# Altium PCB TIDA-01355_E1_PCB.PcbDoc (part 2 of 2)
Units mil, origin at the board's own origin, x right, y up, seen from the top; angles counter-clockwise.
Board outline 2150 x 1600 mil, 4 copper layers (Top Layer, GND, PWR, Bottom Layer), stack 59.906 mil thick; 85 components, 55 nets, 272 pads, 126 vias.
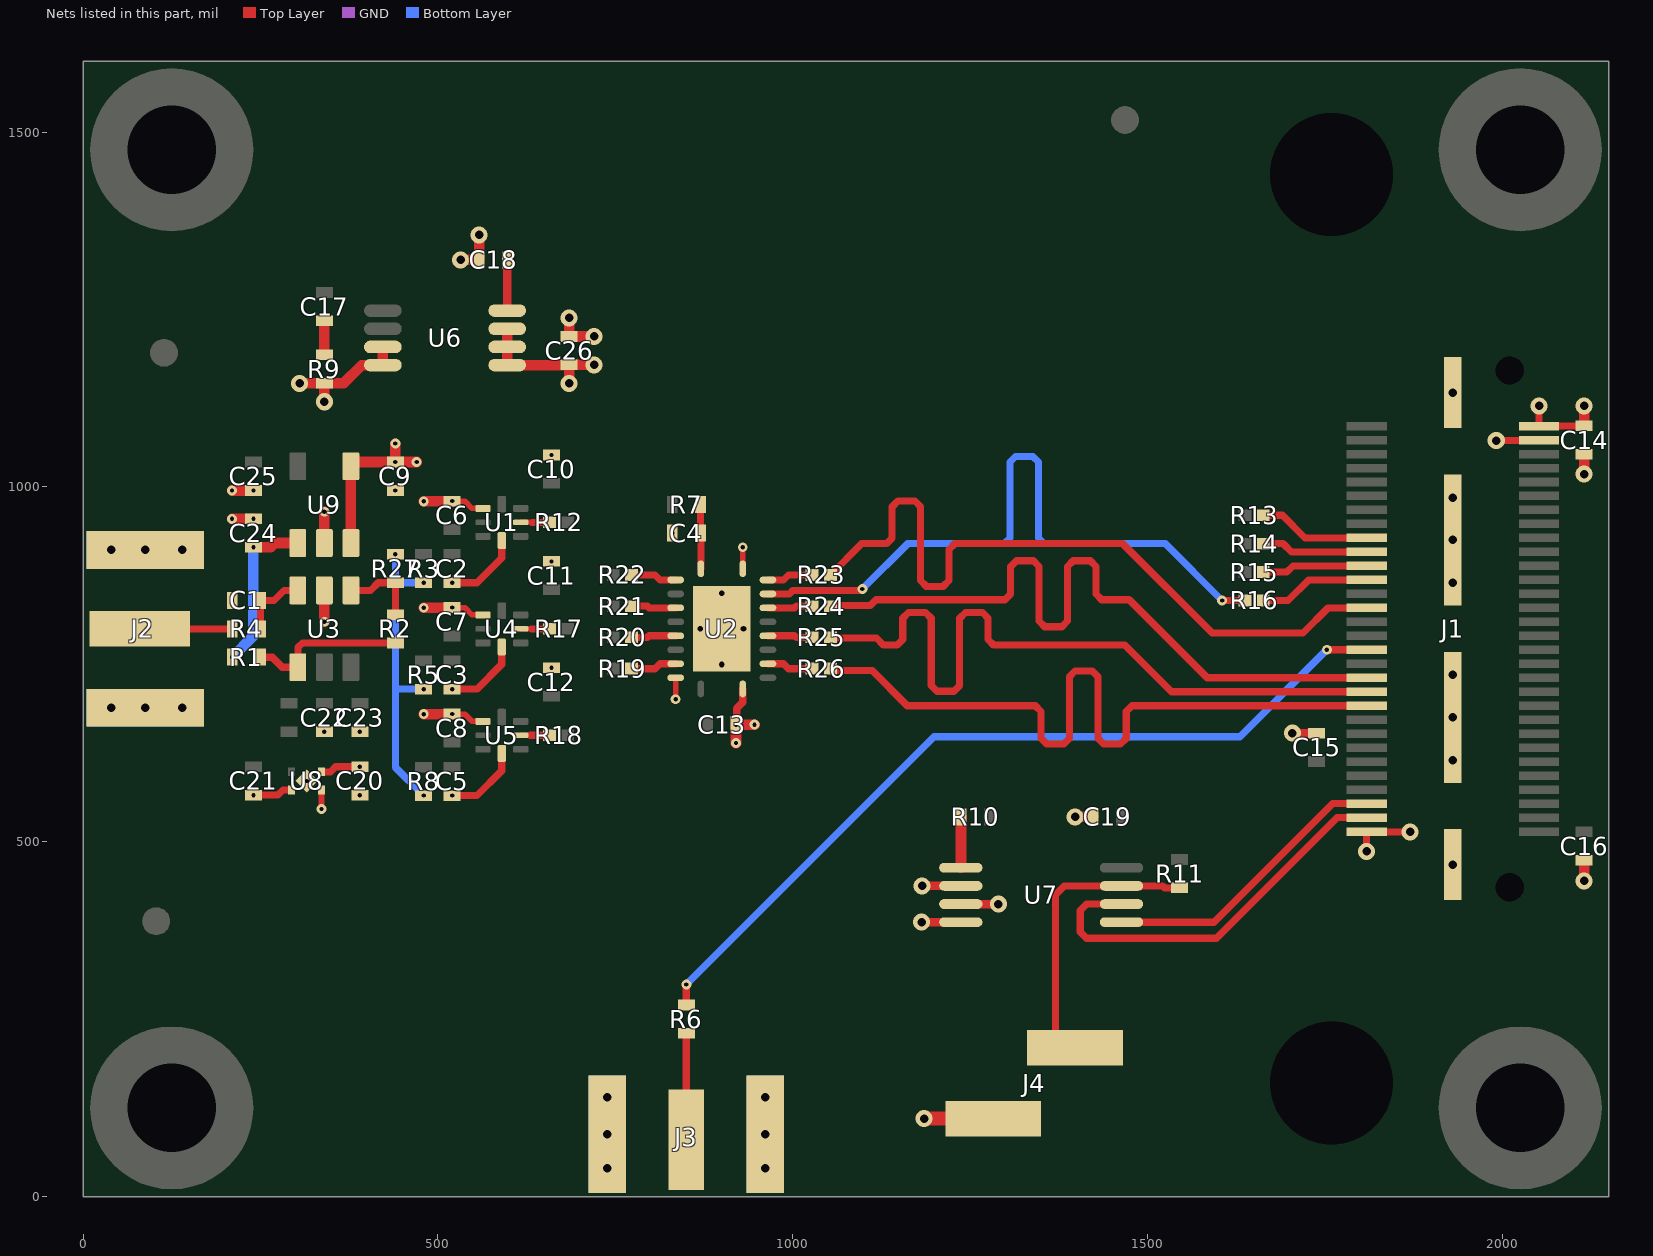
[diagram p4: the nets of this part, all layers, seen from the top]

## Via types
v1: diameter 14, hole 6, Top Layer to Bottom Layer, 70 vias
v2: diameter 24, hole 12, Top Layer to Bottom Layer, 52 vias
v3: diameter 19.68, hole 7.87, Top Layer to Bottom Layer, 4 vias

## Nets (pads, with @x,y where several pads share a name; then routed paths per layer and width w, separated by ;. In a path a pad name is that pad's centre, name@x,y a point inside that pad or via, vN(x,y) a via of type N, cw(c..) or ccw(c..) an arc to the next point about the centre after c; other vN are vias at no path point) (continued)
EVM_ID_SCL: J1.58 U7.6 | length 569.7
  Top Layer w10.06: U7.6@1463.19,412.2 1414.2,412.2 1405,403 1405,373 1414.02,363.98 1596.98,363.98 1767.1,534.1 J1.58@1808.5,534.1
EVM_ID_SDA: J1.56 U7.5 | length 414.6
  Top Layer w10.06: U7.5@1463.19,386.61 1593.61,386.61 1760.8,553.8 J1.56@1808.5,553.8
EVM_REG_5V5: C9.1 C14.1 C20.1 C26.1 J1.1 U6.1 U6.2 U6.3 U8.3 U8.4 U9.3 U9.4 | length 628.3
  Top Layer w8: v1(336.06,546) U8.3@336.06,572.87
  Top Layer w10: U8.4@336.06,598.46 348.46,598.46 355.67,605.67 v1(390,605.67) ; J1.1@2051.5,1085.7 C14.1@2115,1085.7 ; J1.1@2051.5,1086 v2(2051.5,1114)
  Top Layer w15: U9.3@377.4,920.87 U9.4@377.4,1029.13 ; U9.4@379,1035 v1(440,1035) ; v1(440,1061) v1(440,1035) ; v1(470,1035) v1(440,1035) ; U6.3@597.6,1222.8 U6.2@597.6,1197.21 U6.1@597.6,1171.62 684.62,1171.62 C26.1@685,1172 ; v2(685,1146) C26.1@685,1172 ; v2(720,1172) C26.1@685,1172 ; C14.1@2115,1086 v2(2115,1114)
FB_SCLK: C4.1 R7.2 U2.11 | length 90.5
  Top Layer w10.06: R7.2@870,975 C4.1@870,935 870.48,934.52 U2.11@870.48,884.65
GND: C1.2 C2.2 C3.2 C4.2 C5.2 C6.2 C7.2 C8.2 C9.2 C10.2 C11.2 C12.2 C13.2 C14.2 C15.2 C16.2 C18.2 C19.2 C20.2 C21.2 C22.2 C23.2 C24.2 C25.2 C26.2 J1.3 J1.60 J1.MP1 J1.MP2 J1.MP3 J1.MP4 J2.2 J2.3 J2.4 J2.5 J3.2 J3.3 J3.4 J3.5 J4.2 R9.1 U1.5 U1.8 U2.1 U2.10 U2.19 U2.21 U3.2 U4.5 U4.8 U5.5 U5.8 U6.7 U6.8 U7.2 U7.3 U7.4 U8.2 U8.5 U9.2 | length 1793.7
  Top Layer w8: C8.2@520,679.69 538,679.69 548,669.69 U5.5@563.43,669.69 ; C7.2@520,829.69 538,829.69 548,819.69 U4.5@563.43,819.69 ; C6.2@520,979.69 538,979.69 548,969.69 U1.5@563.43,969.69 ; v1(835.04,700.75) U2.19@835.04,731.1 ; U2.10@929.53,884.65 v1(929.53,915)
  Top Layer w10: v1(240,565.67) 274.33,565.67 281.54,572.87 U8.2@293.94,572.87 ; C13.2@921.01,666 921.01,688 929.53,696.52 U2.1@929.53,715.36 ; v2(1808.5,486.4) J1.60@1808.5,514.4 1808.9,514 v2(1870,514) ; v2(1991.23,1065.17) 2052.33,1065.17 J1.3@2051.5,1066
  Top Layer w10.06: v1(520,565) 555,565 590,600 U5.8@590,624.41 ; v1(520,715) 555,715 590,750 U4.8@590,774.41 ; v1(520,865) 555,865 590,900 U1.8@590,924.41
  Top Layer w12: v2(1181.61,386.61) U7.4@1236.81,386.61 ; v2(1182.21,437.79) U7.2@1236.81,437.79 ; U7.3@1236.81,412.2 v2(1289.8,412.2) ; v2(1704,653) C15.2@1738,653
  Top Layer w15: v1(210,955) v1(240,955) ; v1(210,995) v1(240,995) ; v2(305,1146) R9.1@340,1146 ; v1(340,810) U3.2@340,854.14 ; U9.2@340,920.87 v1(340,965) ; v2(340,1120) R9.1@340,1146 ; U6.7@422.4,1197.21 U6.8@422.4,1171.62 392.6,1171.62 366.99,1146 R9.1@340,1146 ; v1(480,679.69) C8.2@520,679.69 ; v1(480,829.69) C7.2@520,829.69 ; v1(480,979.69) C6.2@520,979.69 ; v2(532,1320) C18.2@558,1320 v2(558,1355) ; v2(685,1238) C26.2@685,1212 v2(720,1212) ; v1(920,639) v1(920,665) v1(946,665) ; v2(1398,535) C19.2@1423,535 ; v2(2115,445) C16.2@2115,474 ; v2(2115,1018) C14.2@2115,1046
  Top Layer w20: v2(1185,110) J4.2@1282.52,110
  GND w15: v2@1179,384 v2(1181.61,386.61)
  other v1: 390,565.67 315,585.67 340,655 390,655 520,680 660,745 520,830 210,840 660,895 830,935 520,980 440,995 660,1045
  other v2: 738.56,40 961,40 738.78,87.68 961.22,87.68 738.56,140 961,140 1930,467.7 1930,615 1930,675.2 40,689 87.68,688.78 140,689 1930,735 1930,865 40,911.44 87.68,911.22 140,911.44 1930,925.2 1930,985 1930,1132.7
  other v3: 900,749.81 869.49,800 930.51,800 900,850.2
NetC1_1: C1.1 R4.2 U3.3 | length 98.5
  Top Layer w10.06: R4.2@250,800 C1.1@250,840 269,840 283.14,854.14 U3.3@302.6,854.14
NetC17_2: C17.2 R9.2 | length 45
  Top Layer w15: R9.2@340,1186 C17.2@340,1231
NetC18_1: C18.1 U6.4 | length 71.8
  Top Layer w12: U6.4@597.6,1248.39 597.6,1319.6 C18.1@598,1320
NetJ1_18: J1.18 R13.2 | length 158.7
  Top Layer w10.06: R13.2@1662.99,960 1690,960 1721.9,928.1 J1.18@1808.5,928.1
NetJ1_20: J1.20 R14.2 | length 150.3
  Top Layer w10.06: R14.2@1662.99,920 1691,920 1702.6,908.4 J1.20@1808.5,908.4
NetJ1_22: J1.22 R15.2 | length 149.1
  Top Layer w10.06: R15.2@1662.99,880 1696,880 1704.7,888.7 J1.22@1808.5,888.7
NetJ1_24: J1.24 R16.2 | length 157.5
  Top Layer w10.06: R16.2@1662.99,840 1698,840 1727,869 J1.24@1808.5,869
NetJ2_1: J2.1 R4.1 | length 130.2
  Top Layer w10.06: J2.1@79.8,800 R4.1@210,800
NetJ3_1: J3.1 R6.1 | length 150.2
  Top Layer w10.06: J3.1@850,79.8 R6.1@850,230
NetR1_2: R1.2 R2.1 U3.4 | length 226.2
  Top Layer w10.06: R1.2@250,760 266.5,760 280.63,745.87 U3.4@302.6,745.87 302.6,773.6 309,780 R2.1@440,780
NetR2_2: R2.2 R27.1 U3.1 | length 112.1
  Top Layer w10.06: U3.1@377.4,854.14 405.14,854.14 416,865 R27.1@440,865 R2.2@440,820
NetR10_1: R10.1 U7.1 | length 71.7
  Top Layer w15: U7.1@1236.81,463.39 1237,463.57 R10.1@1237,535
NetR12_1: R12.1 U1.2 | length 40.4
  Top Layer w8: U1.2@616.57,950 633,950
  Top Layer w10.06: 633,950 R12.1@657.01,950
NetR17_1: R17.1 U4.2 | length 43.9
  Top Layer w8: U4.2@616.57,800 632,800
  Top Layer w10.06: 632,800 654.54,800 657.01,802.47 R17.1@657.01,800
NetR18_1: R18.1 U5.2 | length 40.4
  Top Layer w8: U5.2@616.57,650 630,650
  Top Layer w10.06: 630,650 R18.1@657.01,650
NetR19_2: R19.2 U2.18 | length 65
  Top Layer w10.06: R19.2@772.99,743.69 806,743.69 813.1,750.79 U2.18@835.04,750.79
NetR20_2: R20.2 U2.16 | length 63.1
  Top Layer w10.06: R20.2@772.99,787.69 795,787.69 797.47,790.16 U2.16@835.04,790.16
NetR21_2: R21.2 U2.14 | length 63.1
  Top Layer w10.06: R21.2@772.99,832 795,832 797.47,829.53 U2.14@835.04,829.53
NetR22_2: R22.2 U2.12 | length 65
  Top Layer w10.06: R22.2@772.99,876 806,876 813.1,868.9 U2.12@835.04,868.9
NetR23_2: R23.2 U2.9 | length 65
  Top Layer w10.06: U2.9@964.96,868.9 986.91,868.9 994.01,876 R23.2@1027.01,876
NetR24_2: R24.2 U2.7 | length 63.1
  Top Layer w10.06: U2.7@964.96,829.53 1002.54,829.53 1005.01,832 R24.2@1027.01,832
NetR25_2: R25.2 U2.5 | length 63.1
  Top Layer w10.06: U2.5@964.96,790.16 1002.54,790.16 1005.01,787.69 R25.2@1027.01,787.69
NetR26_2: R26.2 U2.3 | length 65
  Top Layer w10.06: U2.3@964.96,750.79 986.91,750.79 994.01,743.69 R26.2@1027.01,743.69
OPA_OUT: R3.2 R5.2 R8.2 R27.2 | length 436.6
  Bottom Layer w10.06: v1(440,905) 440,865 ; v1(480,565) 440,605 440,715 ; v1(480,715) 440,715 ; v1(480,865) 440,865 ; 440,715 440,865
PSYNC: J1.34 R6.2 | length 1182.8
  Top Layer w10.06: R6.2@850,270 v1(850,299) ; v1(1752.5,770.5) J1.34@1808.5,770.5
  Bottom Layer w10.06: v1(850,299) 1199,648 1630,648 v1(1752.5,770.5)
RTN_SCLK: J1.28 R23.1 | length 1053
  Top Layer w10.06: R23.1@1052.99,876 1096.99,920 1132.02,920 1140.03,928.01 1140.03,972.1 1148.04,980.12 1172.08,980.12 1180.1,972.1 1180.1,920 1180.1,867.9 1188.11,859.88 1212.15,859.88 1220.16,867.9 1220.16,911.99 1228.17,920 1235,920 1465,920 1591,794 1719,794 1754.6,829.6 J1.28@1808.5,829.6
SCLK: R16.1 U2.8 | length 963.7
  Top Layer w10.06: U2.8@964.96,849.22 995.39,849.22 1000.01,853.83 1095.83,853.83 v1(1098,856) ; v1(1605,840) R16.1@1637.01,840
  Bottom Layer w10.06: v1@1100,856 v1(1098,856) 1162,920 1286,920 1298.02,920 1306.03,928.01 1306.03,1034.96 1314.04,1042.97 1338.08,1042.97 1346.1,1034.96 1346.1,928.01 1354.11,920 1370,920 1525,920 v1(1605,840)
SDO_A: J1.38 R24.1 | length 1064.1
  Top Layer w10.06: R24.1@1052.99,832 1052.99,833.09 1109.49,833.09 1117.39,841 1287,841 1299.02,841 1307.03,849.01 1307.03,887.99 1315.04,896 1339.08,896 1347.1,887.99 1347.1,841 1347.1,810.89 1355.11,802.87 1379.15,802.87 1387.16,810.89 1387.16,841 1387.16,887.99 1395.17,896 1419.21,896 1427.22,887.99 1427.22,849.01 1435.24,841 1437,841 1474,841 1583.9,731.1 J1.38@1808.5,731.1
SDO_B: J1.40 R25.1 | length 1063.9
  Top Layer w10.06: R25.1@1052.99,788 1054.06,786.94 1118,786.94 1127.94,777 1135,777 1147.02,777 1155.03,785.01 1155.03,815.05 1163.04,823.06 1187.08,823.06 1195.1,815.05 1195.1,777 1195.1,720.01 1203.11,712 1227.15,712 1235.16,720.01 1235.16,777 1235.16,815.05 1243.17,823.06 1267.21,823.06 1275.22,815.05 1275.22,785.01 1283.24,777 1306,777 1468,777 1533.6,711.4 J1.40@1808.5,711.4
SDO_C: J1.42 R26.1 | length 1052.8
  Top Layer w10.06: R26.1@1052.99,744 1055.9,741.09 1111.91,741.09 1161.3,691.7 1320,691.7 1341.76,691.7 1349.78,683.69 1349.78,645.84 1357.79,637.83 1381.83,637.83 1389.84,645.84 1389.84,691.7 1389.84,732.52 1397.85,740.54 1421.89,740.54 1429.9,732.52 1429.9,691.7 1429.9,645.84 1437.92,637.83 1461.96,637.83 1469.97,645.84 1469.97,683.69 1477.98,691.7 1490,691.7 J1.42@1808.5,691.7
VBIAS: C24.1 R1.1 U9.1 | length 232.5
  Top Layer w15: v1(240,915) 264,915 269.87,920.87 U9.1@302.6,920.87
  Bottom Layer w15: v1(210,760) 240,790 v1(240,915)
WP: J4.1 R11.1 U7.7 | length 424.1
  Top Layer w10.06: J4.1@1397.48,210 1370,210 1370,425.31 1382.48,437.79 U7.7@1463.19,437.79 1521.21,437.79 1524,435 R11.1@1545,435
pads on no net: FID1.1 FID2.1 FID3.1 H1.1 H2.1 H3.1 H4.1 H5. H6. J1.2 J1.4 J1.5 J1.6 J1.7 J1.8 J1.9 J1.10 J1.11 J1.12 J1.13 J1.14 J1.15 J1.16 J1.17 J1.19 J1.21 J1.23 J1.25 J1.26 J1.27 J1.29 J1.30 J1.31 J1.32 J1.33 J1.35 J1.36 J1.37 J1.39 J1.41 J1.43 J1.44 J1.45 J1.46 J1.47 J1.48 J1.49 J1.51 J1.52 J1.53 J1.54 J1.55 J1.57 J1.MH1 J1.MH2

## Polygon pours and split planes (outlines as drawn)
AVDD on PWR "PWR_AVDD_P006" (solid, remove dead copper, pour order 6): 170,1172.31 170,906 480,596 544,596 544,1000 360,1000 360,1320 289.49,1320
EVM_ID_PWR on PWR "PWR_EVM_ID_PWR_P021" (solid, remove dead copper, pour order 21): 1200,580 1200,360 2150,360 2150,580 1970,580 1880,490 1610,490 1520,580 1200,580
EVM_DVDD on PWR "PWR_EVM_DVDD_P023" (solid, remove dead copper, pour order 23): 2150,580 1970,580 1880,490 1610,490 1520,580 1200,580 640,580 640,1060 1075,1060 1365,770 2150,770
EVM_REG_5V5 on PWR "PWR_EVM_REG_5V5_P025" (solid, remove dead copper, pour order 25): 2150,1 2150,1600 0,1600 0,0 2150,0
GND on GND "GND_GND_P017" (solid, remove dead copper, pour order 17): 0,0 0,1600 2150,1600 2150,0

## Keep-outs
Keep-Out Layer:
  lines w10: 0,0 0,1600 2150,1600 2150,1 2149,0 0,0
  text ".Layer_Name" at 577,-858.49 h60

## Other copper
Top Layer:
  text ".Layer_Name" at 577,-858.49 h60
GND:
  text ".Layer_Name" at 588,-865 h60
PWR:
  text ".Layer_Name" at 588,-865 h60
Bottom Layer:
  text ".Layer_Name" at 577,-858.49 h60

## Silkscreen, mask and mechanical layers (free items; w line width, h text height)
Top Overlay:
  circle w6: c2092,1085.7 r4.81
  region: 1526,1050 1226,1050 1226,950 1526,950
  lines w5: 263,784 269,778 269,735 ; 465,944 465,934 470,929 470,920 ; 758,720 758,689 ; 1038,900 1038,947 ; 758,689 750,697 766,697 758,689 ; 1038,947 1030,939 1046,939 1038,947
  lines w10: 200,735 200,540 1075,540 1075,1060 200,1060 200,865
  text ".Layer_Name" at 577,-858.49 h60
Bottom Overlay:
  text ".Layer_Name" at 577,-858.49 h60
Top Paste:
  text ".Layer_Name" at 577,-858.49 h60
Bottom Paste:
  text ".Layer_Name" at 577,-858.49 h60
Top Solder:
  text ".Layer_Name" at 577,-858.49 h60
  text ".Layer_Name" at 577,-858.49 h60
Bottom Solder:
  text ".Layer_Name" at 577,-858.49 h60
Drill Guide:
  text ".Layer_Name" at 577,-858.49 h60
M1 Board Outline:
  the board outline again, w10
M2 Board Dimensions:
  rectangle: 0,-275 125,-150
  rectangle: 125,-400 500,-275
  lines w7: 0,-275 1000,-275 ; 125,-400 125,-150 ; 250,-400 250,-150 ; 500,-400 500,-150 ; 750,-400 750,-150 ; 0,-400 1000,-400 1000,-150 0,-150 0,-400
M3 3D STEP Top:
  text ".Layer_Name" at 577,-858.49 h60
M4 3D STEP Bottom:
  text ".Layer_Name" at 577,-858.49 h60
M5 Assembly Top:
  circle w6: c2085,1085 r8
  circle w6: c1464,211 r8
  lines w10: -292,-930.17 6308,-930.17 ; -292,-726.83 6310,-726.83 ; -292,-523.5 -292,-1133.5 3713,-1133.5 6310,-1133.5 6310,-523.5 -291.5,-523.5 -291.5,-1133.5 1284,-1133.5 ; 2173,-1133.5 2173,-523.5 ; 3440,-726.83 3440,-523.5 ; 4280,-726.83 4280,-523.5 ; 4902,-1140 4902,-937.17
  text "COMPONENTS MARKED 'DNP' SHOULD NOT BE POPULATED." at 1153.5,-318.5 h60
  text "ASSEMBLY VARIANT:" at 1153,-434 h60
  text ".VariantName" at 2189,-434 h60
  text "PCB VIEWED FROM TOP SIDE" at -228.5,-655.67 h60
  text "BOARD #:" at 2248,-655.67 h60
  text ".PRJ_Number" at 2793.5,-655.67 h60
  text "REV:" at 3638,-655.67 h60
  text ".PCB_Rev" at 3929.5,-655.67 h60
  text "SVN REV:" at 4476,-655.67 h60
  text ".VersionControl_RevNumber" at 4982,-655.67 h60
  text "LAYER NAME =" at -228.5,-858.49 h60
  text "TID #:" at 2248,-859 h60
  text ".TID" at 2793.5,-859 h60
  text ".Layer_Name" at 588,-865 h60
  text ".plot_File_Name" at 434,-1060 h60
  text "PLOT NAME =" at -228.5,-1064.34 h60
  text "TEXAS INSTRUMENTS" at 5113,-1064.34 h60
  text "GENERATED    :" at 2566.5,-1068 h60
  text ".Print_Date" at 3436,-1068 h60
  text ".Print_Time" at 4165,-1068 h60
M6 Assembly Bottom:
  lines w10: -292.5,-727.33 6309.5,-727.33 ; -290.5,-930.67 6309.5,-930.67 ; 1115.5,-1140.5 1115.5,-937.67 ; 1737.5,-727.33 1737.5,-524 ; 2577.5,-727.33 2577.5,-524 ; 3844.5,-1134 3844.5,-524 ; 4733.5,-1134 6309,-1134 6309,-524 -292.5,-524 -292.5,-1134 2304.5,-1134 6309.5,-1134 6309.5,-524
  text "COMPONENTS MARKED 'DNP' SHOULD NOT BE POPULATED." at 6102,-318 h60
  text ".VariantName" at 5058,-434 h60
  text "ASSEMBLY VARIANT:" at 6097,-434 h60
  text ".VersionControl_RevNumber" at 1035.5,-656.17 h60
  text "SVN REV:" at 1541.5,-656.17 h60
  text ".PCB_Rev" at 2088,-656.17 h60
  text "REV:" at 2379.5,-656.17 h60
  text ".PRJ_Number" at 3224,-656.17 h60
  text "BOARD #:" at 3769.5,-656.17 h60
  text "PCB VIEWED FROM BOTTOM SIDE" at 6246,-656.17 h60
  text ".TID" at 3224,-859.5 h60
  text "TID #:" at 3769.5,-859.5 h60
  text ".Layer_Name" at 5518,-862 h60
  text "LAYER NAME =" at 6267,-862 h60
  text "TEXAS INSTRUMENTS" at 904.5,-1064.84 h60
  text ".Print_Time" at 2169,-1064.84 h60
  text ".Print_Date" at 2898,-1064.84 h60
  text "GENERATED    :" at 3767.5,-1064.84 h60
  text ".plot_File_Name" at 5440.5,-1064.84 h60
  text "PLOT NAME =" at 6246,-1064.84 h60
M9 Title Sheet:
  drawing of 58 lines, arcs and shapes, not listed
  text "1" at 739.84,8036.5 h70
  text "2" at 3235.5,8036.5 h70
  text "3" at 5724.84,8036.5 h70
  text "4" at 8231.51,8036.5 h70
  text "5" at 10730.5,8036.5 h70
  text "6" at 13235.5,8036.5 h70
  text "A" at -416.5,6893.5 h70
  text "A" at 14383.5,6893.5 h70
  text "B" at -416.5,4513.5 h70
  text "B" at 14383.5,4513.5 h70
  text "C" at -416.5,2138.5 h70
  text "C" at 14383.5,2138.5 h70
  text "PROJECT TITLE:" at 11343.5,277.5 h45
  text ".PRJ_Title" at 11393.5,144.17 h70
  text "DESIGNED FOR:" at 11343.5,-23.5 h45
  text ".PRJ_Customer" at 11393.5,-163.5 h70
  text "D" at -416.5,-231.5 h70
  text "D" at 14383.5,-231.5 h70
  text "FILE NAME:" at 11343.5,-323.5 h45
  text ".PCB_File_Name_No_Path" at 11393.5,-443.5 h70
  text "Texas Instruments (TI) and/or its licensors do not warrant the accuracy or completeness of this specification" at 6374,-605.34 h45
  text "ENGINEER:" at 11343.5,-613.5 h45
  text "LAYOUT BY:" at 12848.5,-613.5 h45
  text "or any information contained therein. TI and/or its licensors do not warrant that this design will meet" at 6329.01,-718 h45
  text ".PRJ_Engineer" at 11393.5,-768.49 h70
  text ".PCB_Layout" at 12899,-768.49 h70
  text "the specifications, will be suitable for your application or fit for any particular purpose, or will operate in" at 6329.01,-830.67 h45
  text "ALTIUM DESIGNER VERSION:" at 12848.5,-923.5 h45
  text "an implementation. TI and/or its licensors do not warrant that the design is production worthy. You should" at 6329.01,-943.33 h45
  text "completely validate and test your design implementation to confirm the system functionality for your application." at 6374,-1056 h45
  text ".print_Scale" at 11393.5,-1056.83 h70
  text ".Application_BuildNumber" at 12899,-1056.83 h70
  text "1" at 739.84,-1263.5 h70
  text "2" at 3235.5,-1263.5 h70
  text "3" at 5724.84,-1263.5 h70
  text "4" at 8231.51,-1263.5 h70
  text "5" at 10730.5,-1263.5 h70
  text "6" at 13235.5,-1263.5 h70
M10 Fab Notes:
  drawing of 228 lines, arcs and shapes, not listed
  text "DESIGN INFORMATION" at 12380.92,6834.03 h60
  text "(REFER ALSO ARRAY/PANEL PROFILING INFORMATION)" at 12019.36,6672.32 h60
  text "BOARD SIZE" at 11333.36,6668.03 h60
  text "54.61MM" at 11795.68,6540.21 h60
  text "X" at 12301.36,6540.21 h60
  text "40.64MM" at 12532.68,6540.21 h60
  text "Number of Layers :" at 11736.36,6343.03 h60
  text "4" at 12831.17,6333.04 h60
  text "8" at 12810,6206 h60
  text "MIN. TRACK WIDTH:" at 11736.36,6204.03 h60
  text "MIL" at 12987.36,6204.03 h60
  text "MIL" at 12988,6087 h60
  text "4.706" at 12694,6079 h60
  text "MIN. CLEARANCE:" at 11736.36,6072.03 h60
  text "MIL" at 12991,5953 h60
  text "6" at 12831,5950 h60
  text "MIN. VIA DRILL SIZE:" at 11736.36,5940.03 h60
  text "MINIMUM ANNULAR RING" at 11407.13,5794.04 h60
  text "EXTERNAL" at 13139.36,5794.04 h60
  text "4 MIL" at 12451,5792 h60
  text "PER" at 11607.13,5676.04 h60
  text "IPC-D-275 CLASS 2 LEVEL C" at 11827.13,5676.03 h60
  text "MIL, HOLES" at 13315.36,5563.75 h60
  text "+/-" at 12922.9,5563.04 h60
  text "+/-" at 13776.9,5563.04 h60
  text "REGISTRATION TOLERANCES:" at 11407.13,5558.03 h60
  text "METAL" at 12606.9,5558.03 h60
  text "5" at 13183.1,5558.04 h60
  text "3" at 14016.1,5558.04 h60
  text "MIL" at 14132.36,5558.03 h60
  text "MATERIAL:" at 11332.36,5348.58 h60
  text "FR-4 High Tg" at 12318.8,5208.24 h60
  text "FR-408" at 11753.36,5199.67 h60
  text "X" at 12159.9,5200.03 h60
  text "OTHER" at 13241.36,5199.67 h60
  text "63 MIL (1.6mm) +/-10%" at 12073.46,5036.96 h60
  text "THICKNESS:" at 11407.13,5032.67 h60
  text "X" at 11945.3,5032.67 h60
  text "OTHER" at 13358.36,5032.67 h60
  text "TOLERANCE:" at 11407.13,4874.67 h60
  text "X" at 12246.43,4874.67 h60
  text "ANSI IPC-6012 TYPE 3 CLASS 2" at 12433.38,4874.67 h60
  text "OTHER +/-" at 12433.36,4718.67 h60
  text "BOW & TWIST:" at 11407.13,4561.67 h60
  text "X" at 12246.43,4561.67 h60
  text "ANSI IPC-6012 TYPE 3 CLASS 2" at 12433.38,4561.67 h60
  text "OTHER +/-" at 12433.36,4403.17 h60
  text "COPPER THICKNESS (FINISHED):" at 11332.36,4267.67 h60
  text "1.4MIL (1oz)" at 12212.36,4114.96 h60
  text "2MIL (1.4oz)" at 12979.36,4114.96 h60
  text "2.8MIL (2oz)" at 13706.36,4114.96 h60
  text "OUTER:" at 11689.36,4110.67 h60
  text "X" at 12083.9,4110.03 h60
  text "1.4MIL (1oz)" at 12212.36,3957.96 h60
  text "2.8MIL (2oz)" at 12979.36,3957.96 h60
  text "N/A" at 13705.9,3958.32 h60
  text "INNER SIGNAL:" at 11400.28,3953.67 h60
  text "X" at 12082.9,3952.03 h60
  text "DRILLING:" at 11332.36,3814.67 h60
  text "REFERENCE:" at 11407.13,3697.67 h60
  text "X" at 12055.36,3697.67 h60
  text "AS SHOWN" at 12242.36,3697.67 h60
  text "X" at 12956.36,3697.67 h60
  text "NC_DRILL FILES" at 13093.36,3697.67 h60
  text "PTH MIN COPPER THICKNESS:" at 11407.13,3539.67 h60
  text "X" at 12757.36,3539.67 h60
  text "1MIL" at 12894.36,3539.67 h60
  text "OTHER" at 13391.36,3539.67 h60
  text "BOARD FINISH:" at 11332.36,3380.67 h60
  text "SILKSCREEN:" at 11487.58,3262.67 h60
  text "X" at 12436.36,3262.67 h60
  text "TOP" at 12562.36,3262.67 h60
  text "BOTTOM" at 13073.36,3262.67 h60
  text "SILKSCREEN COLOR:" at 11487.58,3095.67 h60
  text "X" at 12435.32,3095.67 h60
  text "WHITE" at 12562.36,3095.67 h60
  text "OTHER" at 13073.36,3095.67 h60
  text "SOLDER RESIST COLOR:" at 11487.58,2925.67 h60
  text "X" at 12055.32,2766.48 h60
  text "GREEN" at 12182.36,2766.48 h60
  text "BLUE" at 12773.36,2766.48 h60
  text "OTHER" at 13311.36,2766.48 h60
  text "IMMERSION GOLD (ENIG)" at 12393.36,2577.96 h60
  text "ENEPIG" at 13730.9,2574.67 h60
  text "SURFACE FINISH:" at 11332.36,2573.67 h60
  text "X" at 12206.41,2573.67 h60
  text "IMM. TIN/SILVER OR EQUIV" at 11661.9,2416.67 h60
  text "OTHER" at 13093.36,2416.67 h60
  text "ARRAY/PANEL:" at 11332.36,2237.67 h60
  text "CUT AND TRIM PER MECH LAYER 1" at 12393.36,2233.39 h60
  text "NOTE :" at 169.9,2145.03 h60
  text "1. VIAS ON PAD TO BE FILLED WITH CONDUCTIVE MATERIAL" at 483,2139 h60
  text "N.C. ROUTE" at 12393.36,2081.67 h60
  text "V. SCORE" at 13259.36,2081.67 h60
  text "2. 10.064mil TRACE WIDTH ROUTED AS 50 OHM IMPEDANCE ON TOP LAYER AND BOTTOM LAYER." at 487,1998 h60
  text "CERTIFICATION:" at 11332.36,1944.67 h60
  text "MATERIALS AND WORKMANSHIP FOR ALL PCBS" at 12057.36,1944.67 h60
  text "PLEASE REFER THE STACKUP FILE. (STACKUP FILE NAME: TEXAS_4L_50_90_100)" at 611,1879 h60
  text "TO MEET OR EXCEED THE REQUIREMENTS OF:" at 12057.36,1846.67 h60
  text "X" at 11683.86,1710.17 h60
  text "ANSI IPC-A-600F CLASS ->" at 11822.86,1710.17 h60
  text "X" at 13461.92,1710.17 h60
  text "2" at 13580.86,1710.17 h60
  text "1" at 13265.86,1708.67 h60
  text "3" at 13934.86,1708.67 h60
  text "X" at 11685.92,1550.67 h60
  text "UL 94V-0" at 11822.86,1550.67 h60
  text "X" at 12497.92,1550.67 h60
  text "RoHS" at 12634.86,1550.67 h60
  text "OTHER" at 13279.26,1550.67 h60
  text "PER ORDER" at 13676.32,1550.67 h60
  text "VIA TENTING:" at 12549.9,1417.03 h60
  text "X" at 13637,1416 h60
  text "ADDITIONAL REQUIREMENTS:" at 11332.36,1409.67 h60
  text "YES" at 13099.57,1407.95 h60
  text "NO" at 13464.37,1402.73 h60
  text "MICROSECTION:" at 11407.13,1294.67 h60
  text "YES" at 12312.86,1294.67 h60
  text "IMPEDANCE CONTROL:" at 12571.9,1288.03 h60
  text "YES" at 13555.9,1287.03 h60
  text "X" at 13778,1287 h60
  text "NO" at 13931.37,1269.73 h60
  text "REQUIRED" at 13174.36,1138.53 h60
  text "BARE BOARD ELEC. TEST:" at 11407.13,1135.67 h60
  text "NONE" at 12712.86,1135.67 h60
  text "X" at 13047.36,1135.67 h60
  text "PER ORDER" at 13766.36,1135.67 h60
  text "MANUFACTURER'S UL:" at 11407.13,978.67 h60
  text "RAIL" at 12572.86,974.39 h60
  text "METAL" at 13064.67,974.39 h60
  text "X" at 13439.9,974.03 h60
  text "SILK" at 13576.36,974.39 h60
M11 Gerber Information:
  lines w10: -292,-930.17 6308,-930.17 ; -292,-726.83 6310,-726.83 ; -292,-523.5 -292,-1133.5 3713,-1133.5 6310,-1133.5 6310,-523.5 -291.5,-523.5 -291.5,-1133.5 1284,-1133.5 ; 2173,-1133.5 2173,-523.5 ; 3440,-726.83 3440,-523.5 ; 4280,-726.83 4280,-523.5 ; 4902,-1140 4902,-937.17
  text "ALL ARTWORK VIEWED FROM TOP SIDE" at -228.5,-655.67 h60
  text "BOARD #:" at 2248,-655.67 h60
  text ".PRJ_Number" at 2793.5,-655.67 h60
  text "REV:" at 3638,-655.67 h60
  text ".PCB_Rev" at 3929.5,-655.67 h60
  text "SVN REV:" at 4476,-655.67 h60
  text ".VersionControl_RevNumber" at 4982,-655.67 h60
  text "LAYER NAME =" at -228.5,-858.49 h60
  text "TID #:" at 2248,-859 h60
  text ".TID" at 2793.5,-859 h60
  text "PLOT NAME =" at -228.5,-1064.34 h60
  text "TEXAS INSTRUMENTS" at 5113,-1064.34 h60
  text ".plot_File_Name" at 445,-1069 h60
  text "GENERATED    :" at 2667.5,-1069 h60
  text ".Print_Date" at 3537,-1069 h60
  text ".Print_Time" at 4266,-1069 h60
M13 Component Bodies Top:
  text ".Layer_Name" at 577,-858.49 h60
M14 Component Bodies Bottom:
  text ".Layer_Name" at 577,-858.49 h60
M15 Courtyards Top:
  text ".Layer_Name" at 577,-858.49 h60
M16 Courtyards Bottom:
  text ".Layer_Name" at 577,-858.49 h60
Drill Drawing:
  text ".legend" at 5724,1505 h60
  text "Drill Table" at 5722,1394 h60
  text "FOR 6MIL DRILL +0/-6MIL" at 5723,1254 h60
  text "FOR 7.874MIL DRILL +0/-7.874MIL" at 5723,1161 h60
  text "FOR 12MIL DRILL +0/-12MIL" at 5724,1067 h60
  text "FOR PTH DRILL +/-3MIL" at 5721,973 h60
  text "FOR NPTH DRILL +/-2MIL" at 5717,880 h60
  text ".Layer_Name" at 577,-858.49 h60
M17 Embedded Cavity:
  text ".Layer_Name" at 577,-858.49 h60
M18 Embedded Assembly:
  text ".Layer_Name" at 577,-858.49 h60
M19 Embedded Keepout:
  text ".Layer_Name" at 577,-858.49 h60

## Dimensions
0,-400 to 1000,-400 on M2 Board Dimensions
0,1600 to 2150,0 on M2 Board Dimensions
2150,0 to 0,1600 on M2 Board Dimensions
1075,1060 to 1075,540 on Top Overlay
200,540 to 1075,540 on Top Overlay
